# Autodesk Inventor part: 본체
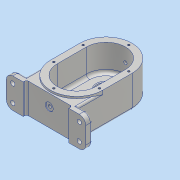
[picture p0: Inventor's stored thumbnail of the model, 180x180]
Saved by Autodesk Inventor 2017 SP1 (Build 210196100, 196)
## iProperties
Part Number: 본체
Material: 알루미늄 6061
Document SubType Name: Modeling
Designer: MRC
Density: 2.7 g/cm^3
Appearance: 알루미늄 - 평지
Mass: 756.242 g
Surface Area: 582.881 cm^2
Volume: 280.09 cm^3
Author: MRC
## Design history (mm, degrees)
sketch "스케치1"
  geometry: L1 (-40, 66)-(40, 66); L2 (40, 66)-(40, -66); L3 (40, -66)-(-40, -66); L4 (-40, -66)-(-40, 66); 3 further points
  constraints: 8 end point, 2 midpoint, 2 parallel, 1 horizontal, 1 horizontal alignment, 1 perpendicular, 1 vertical alignment
  dimensions: "d0" = 80 distance of L1.start L1.end; "d1" = 132 distance of L1.end L2.end
extrude "돌출1" new body sketch "스케치1" distance "d2" = 24.5; taper "d3" = 0 deg; dims "d140" = 21.5, "d141" = 0
fillet "모깎기1" dims "d4" = 40
sketch "스케치2"
  geometry: L1 (-40, -66)-(40, -66) reference; L2 (-61, -66)-(61, -66); L3 (61, -66)-(61, -56); L4 (61, -56)-(-61, -56); L5 (-61, -56)-(-61, -66); 3 further points
  constraints: 8 end point, 3 midpoint, 2 parallel, 1 horizontal, 1 perpendicular, 1 vertical alignment
  dimensions: "d5" = 10 distance between parallel lines of L1 L4; "d6" = 122 distance between parallel lines of L3 L5
extrude "돌출2" join sketch "스케치2" distance "d7" = 46; taper "d8" = 0 deg
sketch "스케치3"
  geometry: L1 (0, 56)-(0, -49); L2 (-30, 26)-(-30, -19); L3 (30, -19)-(30, 26); A1 r 40 centre (0, 26) between (40, 26) and (-40, 26) reference; A2 r 30 centre (0, 26) between (30, 26) and (-30, 26); A3 r 30 centre (0, -19) between (-30, -19) and (30, -19); 2 further points
  constraints: 8 end point, 6 point on circle, 4 tangent, 2 centre point, 2 point on line, 1 coincident, 1 midpoint, 1 parallel, 1 vertical
  dimensions: "d10" = 60 distance between parallel lines of L3 L2; "d11" = 45 distance of A3.centre A2.centre
extrude "돌출3" cut sketch "스케치3" distance "d12" = 38; taper "d13" = 0 deg
sketch "스케치4"
  geometry: L1 (-30, -19)-(-30, 26) reference; L2 (30, 26)-(30, -19) reference; L3 (40, -56)-(40, 26) reference; L4 (-40, 26)-(-40, -56) reference; L5 (0, 66)-(0, -59); L6 (-40, 26)-(-40, -19); L7 (40, -19)-(40, 26); A1 r 30 centre (0, -19) between (-30, -19) and (30, -19) reference; A2 r 30 centre (0, 26) between (30, 26) and (-30, 26) reference; A3 r 40 centre (0, 26) between (40, 26) and (-40, 26) reference; A4 r 40 centre (0, 26) between (40, 26) and (-40, 26); A5 r 40 centre (0, -19) between (-40, -19) and (40, -19); 2 further points
  constraints: 8 end point, 6 point on circle, 4 tangent, 2 centre point, 2 point on line, 1 coincident, 1 midpoint, 1 parallel, 1 vertical
  dimensions: "d14" = 80 distance between parallel lines of L7 L6; "d15" = 45 distance of A5.centre A2.centre
extrude "돌출4" join sketch "스케치4" distance "d16" = 3; taper "d17" = 0 deg
sketch "스케치7"
  geometry: L1 (-40, -66)-(40, -66) reference; L2 (0, 52)-(0, -45); L3 (-26, 26)-(-26, -19); L4 (26, -19)-(26, 26); L5 (-26, -4)-(26, -4); A1 r 40 centre (0, 26) between (40, 26) and (-40, 26) reference; A2 r 26 centre (0, 26) between (26, 26) and (-26, 26); A3 r 26 centre (0, -19) between (-26, -19) and (26, -19); 3 further points
  constraints: 10 end point, 6 point on circle, 4 tangent, 3 point on line, 2 centre point, 2 midpoint, 1 coincident, 1 horizontal, 1 parallel, 1 perpendicular, 1 vertical, 1 vertical alignment
  dimensions: "d24" = 52 distance between parallel lines of L4 L3; "d25" = 30 distance from line of L5 A1.centre; "d26" = 47 distance from line of L1 A3.centre
extrude "돌출6" join sketch "스케치7" distance "d27" = 11; taper "d28" = 0 deg
sketch "스케치9"
  geometry: L1 (-26, 26)-(-26, -19) reference; L2 (26, -19)-(26, 26) reference; L3 (-26, -4)-(26, -4) reference; L4 (-26, -4)-(26, -4); L5 (-26, -19)-(-26, 26) reference; L6 (-26, -4)-(-26, 26); L7 (26, -4)-(26, 26); A1 r 26 centre (0, 26) between (26, 26) and (-26, 26); 1 further point
  constraints: 6 end point, 3 collinear, 2 point on circle, 2 tangent, 1 centre point
extrude "돌출7" cut sketch "스케치9" distance "d29" = 3; taper "d30" = 0 deg
sketch "스케치11"
  geometry: C1 r 14 at (0, 26); A1 r 30 centre (0, 26) between (30, 26) and (-30, 26) reference; 1 further point
  constraints: 1 centre point, 1 coincident
  dimensions: "d32" = 28 diameter of C1
extrude "돌출8" cut sketch "스케치11" distance "d33" = 8; taper "d34" = 0 deg
sketch "스케치13"
  geometry: C1 r 14 at (0, 26); A1 r 26 centre (0, 26) between (26, 26) and (-26, 26) reference; 1 further point
  constraints: 1 centre point, 1 coincident
  dimensions: "d35" = 28 diameter of C1
extrude "돌출9" cut sketch "스케치13" distance "d36" = 4; taper "d37" = 0 deg
sketch "스케치14"
  geometry: C1 r 14 at (0, 0) reference; C2 r 11 at (0, 0); 1 further point
  constraints: 1 centre point, 1 coincident
  dimensions: "d38" = 22 diameter of C2
extrude "돌출10" cut sketch "스케치14" stored distance "d39" = 4; taper "d40" = 0 deg
sketch "스케치15"
  geometry: C1 r 14 at (0, -19); A1 r 30 centre (0, -19) between (-30, -19) and (30, -19) reference; 1 further point
  constraints: 1 centre point, 1 coincident
  dimensions: "d41" = 28 diameter of C1
extrude "돌출11" cut sketch "스케치15" distance "d42" = 8; taper "d43" = 0 deg
sketch "스케치16"
  geometry: C1 r 14 at (0, 0) reference; C2 r 10 at (0, 0); 1 further point
  constraints: 1 centre point, 1 coincident
  dimensions: "d44" = 20 diameter of C2
extrude "돌출12" cut sketch "스케치16" distance "d45" = 4; taper "d46" = 0 deg
sketch "스케치17"
  geometry: L1 (-61, -66)-(61, -66) reference; L2 (-35, -61)-(35, -61); L3 (35, -61)-(35, -66); L4 (35, -66)-(-35, -66); L5 (-35, -66)-(-35, -61); 3 further points
  constraints: 8 end point, 3 midpoint, 2 parallel, 1 horizontal, 1 perpendicular, 1 vertical alignment
  dimensions: "d47" = 5 distance between parallel lines of L1 L2; "d48" = 70 distance between parallel lines of L3 L5
extrude "돌출13" cut sketch "스케치17" stored distance "d49" = 4; taper "d50" = 0 deg
sketch "스케치18"
  geometry: A1 r 30 centre (0, 26) between (30, 26) and (-30, 26) reference; A2 r 30 centre (0, -19) between (-30, -19) and (30, -19) reference; 3 further points
  constraints: 2 vertical alignment
  dimensions: "d51" = 35 distance of A1.centre point (0, 61); "d52" = 35 distance of point (0, -54) A2.centre
hole "구멍1" sketch "스케치18" at (0, 61), (0, -54) diameter "d53" = 3.242; stored, may be unused: countersink angle "d57" = 90 deg, drill point angle "d59" = 118 deg; dims "d54" = 8, "d55" = 4, "d56" = 2, "d58" = 10
sketch "스케치19"
  geometry: A1 r 30 centre (0, 26) between (30, 26) and (-30, 26) reference; A2 r 30 centre (0, -19) between (-30, -19) and (30, -19) reference; 5 further points
  constraints: 4 horizontal alignment
  dimensions: "d60" = 35 distance of A1.centre point (-35, 26); "d61" = 35 distance of point (35, 26) A1.centre; "d62" = 35 distance of A2.centre point (-35, -19); "d63" = 35 distance of point (35, -19) A2.centre
hole "구멍2" sketch "스케치19" at (-35, 26), (35, 26), (-35, -19), (35, -19) diameter "d64" = 3.242; stored, may be unused: countersink angle "d68" = 90 deg, drill point angle "d70" = 118 deg; dims "d65" = 8, "d66" = 4, "d67" = 2, "d69" = 10
node "작업 평면5"
sketch "스케치20"
  geometry: L1 (40, 27.5)-(-40, 27.5) reference; C1 r 6 at (0, 6.5); 1 further point
  constraints: 1 centre point, 1 vertical alignment
  dimensions: "d128" = 12 diameter of C1; "d129" = 21 distance from line of C1.centre L1
extrude "돌출14" join sketch "스케치20" stored distance "d73" = 4; taper "d74" = 0 deg
sketch "스케치21"
  geometry: L1 (75, 3)-(-5, 3) reference; 2 further points
  constraints: 1 vertical alignment
  dimensions: "d84" = 21 distance from line of point (35, -18) L1
hole "구멍4" sketch "스케치21" at (35, -18) diameter "d85" = 4.917; stored, may be unused: countersink angle "d89" = 90 deg, drill point angle "d91" = 118 deg; dims "d86" = 12, "d87" = 12, "d88" = 1, "d90" = 17.1
fillet "모깎기2" dims "d92" = 5
fillet "모깎기3" dims "d93" = 10
sketch "스케치23"
  geometry: A1 r 10 centre (11, 36) between (21, 36) and (11, 46) reference; A2 r 10 centre (11, 10) between (11, 0) and (21, 10) reference; 3 further points
  constraints: 2 coincident
hole "구멍5" sketch "스케치23" at (11, 10), (11, 36) diameter "d94" = 6.6; stored, may be unused: countersink angle "d98" = 90 deg, drill point angle "d100" = 118 deg; dims "d95" = 12, "d96" = 11, "d97" = 2, "d99" = 17.1
fillet "모깎기4" dims "d101" = 3
fillet "모깎기5" dims "d102" = 3
fillet "모깎기6" dims "d103" = 3
fillet "모깎기7" dims "d104" = 3
chamfer "모따기1" distance "d105" = 1; stored, may be unused: second distance "d106" = 2, angle "d107" = 45 deg
fillet "모깎기8" dims "d108" = 0.3
chamfer "모따기2" distance "d109" = 1; stored, may be unused: second distance "d110" = 2, angle "d111" = 45 deg
fillet "모깎기9" dims "d112" = 3
sketch "스케치24"
  geometry: A1 r 26 centre (0, 26) between (26, 26) and (-26, 26) reference; 2 further points
  constraints: 1 vertical alignment
  dimensions: "d114" = 20 distance of A1.centre point (0, 46)
hole "구멍6" sketch "스케치24" at (0, 46) diameter "d115" = 3.242; stored, may be unused: countersink angle "d119" = 90 deg, drill point angle "d121" = 118 deg; dims "d116" = 8, "d117" = 11, "d118" = 2, "d120" = 10
sketch "스케치25"
  geometry: L1 (-51, -66)-(-40, -66) reference; A1 r 37 centre (0, 26) between (37, 26) and (-37, 26) reference; 2 further points
  constraints: 1 vertical alignment, 1 other
  dimensions: "d125" = 12 distance from line of point (0, -54) L1
feature "엠보싱1" sketch "스케치25" dims "d126" = 0.5, "d127" = 0
fillet "모깎기11" dims "d130" = 3
hole "구멍7" diameter "d133" = 4.917; stored, may be unused: countersink angle "d137" = 90 deg, drill point angle "d139" = 118 deg; dims "d131" = 10, "d132" = 10, "d134" = 12, "d135" = 11, "d136" = 2, "d138" = 17.1
node "솔리드1"
mirror "미러1"
pattern_circular "원형 패턴1" dims angle "d123" = 360 deg
